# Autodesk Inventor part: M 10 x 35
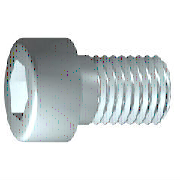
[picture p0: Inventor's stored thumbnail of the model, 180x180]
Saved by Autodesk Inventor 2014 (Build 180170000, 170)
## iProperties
IsCustomPart: 0
Created: 2009-02
Part Number: M 10 x 35
Material: 강, 연강
Description: 6각머리 태핑 나사
Document SubType Name: Modeling
Standard: KS B 1003
Designer: KYOUNG IL JANG
Standards Organization: KS
Language: ko-KR
Size Designation: M 10 x 35
Categories: <MemberInstance><Categories><Category DisplayName="조임쇠" InternalName="e4da775c-781d-43d5-af7c-5136215cf5a6" Mnemonic="FSTN"><Category DisplayName="볼트" InternalN
Density: 7.86 g/cm^3
Appearance: 강철
Mass: 34.5961 g
Surface Area: 21.1658 cm^2
Volume: 4.40154 cm^3
Author: KYOUNG IL JANG
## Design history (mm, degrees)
sketch "스케치1"
  geometry: L1 (-2.333, 0)-(35, 0); L2 (35, 0)-(35, 5); L3 (35, 5)-(3.75, 5); L4 (3.75, 5)-(2.83, 5); L5 (2.83, 5)-(0, 5); L6 (0, 5)-(0, 8); L7 (0, 8)-(-10, 8); L8 (-10, 8)-(-10, 4.619); L9 (-10, 4.619)-(-5, 4.619); L10 (-5, 4.619)-(-2.333, 0); L11 (-19, 0)-(44, 0) reference; L12 (0, -1.6)-(0, 9.6) reference; L13 (3.75, 5)-(0, 5)
  constraints: 22 end point, 6 parallel, 2 collinear, 2 perpendicular, 1 horizontal, 1 point on line
  dimensions: "d1" = 31.25 distance from line of L3.end L2 (= GEL); "d2" = 0.92028 distance of L4.end L3.end (computed from GAL); "d3" = 10 distance between parallel lines of L8 L6 (= KOH); "d4" = 5 distance of L8.end L9.end (= INTI); "d5" = 60 deg angle of L10 L1; "d6" = 10 diameter of L3 L1 (= GD); "d7" = 10 diameter of L5 L1 (= BDM); "d8" = 9.2376 diameter of L9 L1 (= 1.1547 x SW); "d9" = 16 diameter of L7 L1 (= KOD); "d26" = 35 distance between parallel lines of L12 L2 (= NLG)
revolve "본체" sketch "스케치1" stored, may be unused: angle "d10" = 90 deg
sketch "스케치2"
  geometry: L1 (0, -11.2)-(0, 11.2) reference; L2 (-11.2, 0)-(11.2, 0) reference; L3 (4.619, 0)-(2.309, -4); L4 (2.309, -4)-(-2.309, -4); L5 (-2.309, -4)-(-4.619, 0); L6 (-4.619, 0)-(-2.309, 4); L7 (-2.309, 4)-(2.309, 4); L8 (2.309, 4)-(4.619, 0); 2 further points
  constraints: 12 end point, 1 coincident, 1 horizontal alignment, 1 point on line, 12 other
extrude "슬롯" join sketch "스케치2" stored distance "d11" = 10; taper "d12" = 0 deg
workplane "Work Plane1"
fillet "Fillet2" dims "d30" = 0.1 (= R)
body "Solid1"
fillet "모깎기1" dims "d17" = 1 (= RR)
feature "스레드" dims "d13" = 31.25 (= GEL), "d14" = 0
chamfer "모따기1" distance "d15" = 0.92018 (= -0.5 x SPD + 0.5 x GD); stored, may be unused: second distance "d16" = 0.92018 (= GUL), angle "d27" = 45 deg
other parameters: "GD" = 10 (= NND) [user parameter; used in 2 equation terms], "NLG" = 35 [user parameter; used in 1 equation term], "GEL" = 31.25 [user parameter; used in 2 equation terms], "KOD" = 16 [user parameter; used in 1 equation term], "KOH" = 10 [user parameter; used in 1 equation term], "INTI" = 5 [user parameter; used in 1 equation term], "GAL" = 0.92018 (= 0.61345 x PTC) [user parameter; used in 1 equation term], "GUL" = 0.92018 (= 0.61345 x PTC) [user parameter; used in 1 equation term], "BDM" = 10 (= NND) [user parameter; used in 1 equation term], "SW" = 8 [user parameter; used in 2 equation terms], "RR" = 1 [user parameter; used in 1 equation term], "SPD" = 8.15965 (= NND - 1.2269 x PTC) [user parameter; used in 1 equation term], "d19" = 0, "d28" = 0, "d29" = 0, "R" = 0.1 [user parameter; used in 1 equation term], "PHH" = 0.4 [user parameter], "GD1" = 8.15965 (= THREADDIA - 1.2269 x PTC) [user parameter], "FAWI" = 45 deg [user parameter], "TPU" = 6.66667 (computed from PTC) [user parameter], "PTC" = 1.5 [user parameter; used in 5 equation terms], "TOA" = 30 deg [user parameter], "E0" = 9.24 (= 1.155 x SW) [user parameter]
